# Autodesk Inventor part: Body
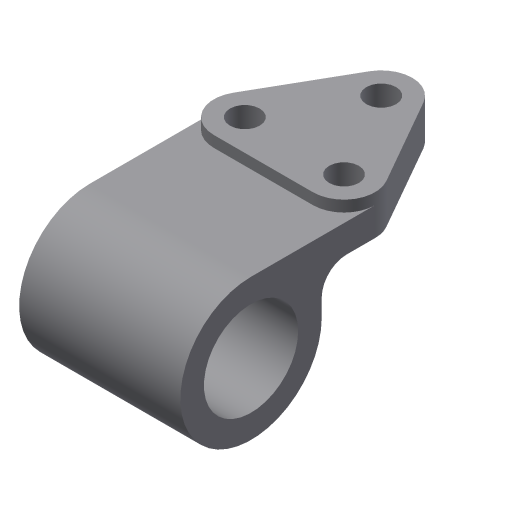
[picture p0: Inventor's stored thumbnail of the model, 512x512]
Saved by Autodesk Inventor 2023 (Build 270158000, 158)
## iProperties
Created: 2010-03
Part Number: Body
Document SubType Name: Modeling
Designer: bhakira
Density: 1 g/cm^3
Material: Generic
Appearance: Default
Author: bhakira
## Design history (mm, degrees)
sketch "Sketch1"
  geometry: L1 (10.853, 41.202)-(30.853, 6.202); L2 (-10.853, 41.202)-(-30.853, 6.202); L3 (-20, -12.5)-(20, -12.5); C1 r 6 at (0, 35); A1 r 12.5 centre (0, 35) between (10.853, 41.202) and (-10.853, 41.202); A2 r 12.5 centre (-20, 0) between (-30.853, 6.202) and (-20, -12.5); A3 r 12.5 centre (20, 0) between (20, -12.5) and (30.853, 6.202); 1 further point
  constraints: 6 end point, 6 point on circle, 6 tangent, 4 centre point, 3 horizontal alignment, 2 equal radius, 1 coincident, 1 vertical alignment, 1 other
  dimensions: "d25" = 35 vertical distance of A1.centre A2.centre; "d27" = 12.5 radius of A1; "d28" = 40 distance of A3.centre A2.centre; "d29" = 20 horizontal distance of A3.centre A1.centre
extrude "Extrusion1" new body sketch "Sketch1" distance "d6" = 16; taper "d7" = 0 deg
workplane "Work Plane2"
workplane "Work Plane3"
sketch "Sketch2"
  geometry: L1 (0, 11.5)-(0, 0); L2 (-12.5, 16)-(6.202, 16) reference; L3 (-50, 11.5)-(0, 11.5); L4 (0, 0)-(-21.5, 0); L5 (-21.5, -17)-(-21.5, 0); L6 (-12.5, 0)-(-12.5, 16) reference; C1 r 19 at (-50, -17); A1 r 28.5 centre (-50, -17) between (-50, 11.5) and (-21.5, -17)
  constraints: 8 end point, 2 centre point, 2 horizontal, 2 point on circle, 2 tangent, 1 coincident, 1 perpendicular, 1 vertical
  dimensions: "d9" = 38 diameter of C1; "d10" = 57 diameter of A1; "d11" = 50 distance from line of L1 C1.centre; "d12" = 33 distance from line of C1.centre L2
extrude "Extrusion2" join sketch "Sketch2" stored distance "d14" = 63.5; taper "d15" = 0 deg
sketch "Sketch3"
  geometry: C1 r 6 at (20, 0) reference; C2 r 6 at (-20, 0) reference; C3 r 6 at (0, 35); 1 further point
  constraints: 1 centre point
extrude "Extrusion3" cut sketch "Sketch3" distance "d16" = 63.5; taper "d17" = 0 deg
node "Sketch4"
hole "Hole1" diameter "d32" = 12; stored, may be unused: countersink angle "d36" = 90 deg, drill point angle "d38" = 118 deg; dims "d33" = 6, "d34" = 4, "d35" = 2082.8, "d37" = 8, "d39" = 10, "d40" = 10
fillet "Fillet1" dims "d42" = 10
body "Solid1"
